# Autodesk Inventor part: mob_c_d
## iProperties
Author: Philippe
Shininess: 20.0
Angle Display Precision: 2
Document Length Units: 11269
Document Angle Units: 11283
Document Time Units: 11279
Document Mass Units: 11290
Document Length Units Precision: 3
Document Angle Units Precision: 2
Compacted: False
PropertySet Name: _Private Model Information
Created: 2002-05
Part Number: mob_c_d
Material: Par défaut
Document SubType Name: Modélisation
Designer: Philippe
Control State: 0
Master: False
Checked Out: False
PropertySet Name: Design Tracking Control
Density: 0.0
Volumn: 0.0
Area: 0.0
PropertySet Name: Model Information
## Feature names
1. Extrusion1
2. Extrusion2
3. Réseau circulaire1 [Circular Pattern]
4. Extrusion3
5. Extrusion4
6. Réseau circulaire2 [Circular Pattern]
7. Perçage2 [Hole]
